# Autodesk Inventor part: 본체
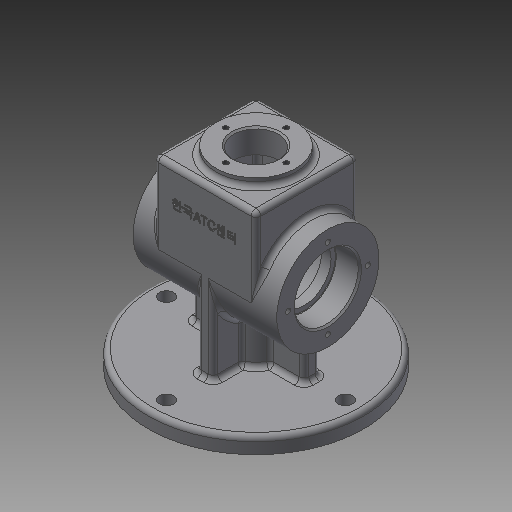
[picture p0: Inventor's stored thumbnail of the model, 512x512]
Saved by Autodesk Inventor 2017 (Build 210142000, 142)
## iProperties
Created: 2020-07
Part Number: 본체
Material: 일반
Document SubType Name: Modeling
Designer: mduedu
Density: 1 g/cm^3
Appearance: 기본값
Author: mduedu
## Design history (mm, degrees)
sketch "스케치1"
  geometry: C1 r 32 at (0, 0); 1 further point
  constraints: 1 centre point, 1 coincident
  dimensions: "d0" = 64 diameter of C1
extrude "돌출1" new body sketch "스케치1" stored distance "d1" = 90; taper "d2" = 0 deg
sketch "스케치3"
  geometry: L1 (0, -32)-(50, -32); L2 (50, -32)-(50, 32); L3 (50, 32)-(0, 32); L4 (0, 32)-(0, -32); C1 r 32 at (0, 0) reference; 2 further points
  constraints: 8 end point, 2 parallel, 1 coincident, 1 horizontal, 1 midpoint, 1 perpendicular, 1 tangent
  dimensions: "d5" = 50 distance of L2.end L3.end
extrude "돌출2" join sketch "스케치3" stored distance "d7" = 64; taper "d8" = 0 deg
sketch "스케치4"
  geometry: C1 r 25 at (32, 32); 1 further point
  constraints: 1 centre point, 1 coincident
  dimensions: "d9" = 50 diameter of C1
extrude "돌출3" join sketch "스케치4" distance "d10" = 5; taper "d11" = 0 deg
sketch "스케치5"
  geometry: L1 (0, -25)-(40, -25); L2 (40, -25)-(40, 25); L3 (40, 25)-(0, 25); L4 (0, 25)-(0, -25); L5 (55, -25)-(55, 25) reference; A1 r 25 centre (0, 0) between (0, 25) and (0, -25); A2 r 25 centre (0, 0) between (0, -25) and (0, 25); 2 further points
  constraints: 8 end point, 4 point on circle, 2 centre point, 2 coincident, 2 parallel, 1 horizontal, 1 midpoint, 1 perpendicular, 1 tangent
  dimensions: "d12" = 50 diameter of A1; "d13" = 15 distance between parallel lines of L2 L5
extrude "돌출4" cut sketch "스케치5" stored distance "d14" = 48; taper "d15" = 0 deg
sketch "스케치6"
  geometry: C1 r 20 at (0, 0); 1 further point
  constraints: 1 centre point, 1 coincident
  dimensions: "d16" = 40 diameter of C1
extrude "돌출5" cut sketch "스케치6" distance "d17" = 15; taper "d18" = 0 deg
sketch "스케치7"
  geometry: C1 r 17 at (0, 0); 1 further point
  constraints: 1 centre point, 1 coincident
  dimensions: "d19" = 34 diameter of C1
extrude "돌출6" cut sketch "스케치7" stored distance "d20" = 15; taper "d21" = 0 deg
fillet "모깎기1" dims "d22" = 3
fillet "모깎기2" dims "d23" = 3
fillet "모깎기3" dims "d24" = 3
fillet "모깎기4" dims "d25" = 3
fillet "모깎기5" dims "d26" = 3
sketch "스케치8"
  geometry: C1 r 14 at (0, 0); 1 further point
  constraints: 1 centre point, 1 coincident
  dimensions: "d27" = 28 diameter of C1
extrude "돌출7" cut sketch "스케치8" stored distance "d28" = 15; taper "d29" = 0 deg
node "작업 평면1"
sketch "스케치9"
  geometry: C1 r 67.5 at (0, 0); 1 further point
  constraints: 1 centre point, 1 coincident
  dimensions: "d31" = 135 diameter of C1
extrude "돌출8" join sketch "스케치9" distance "d33" = 10; taper "d34" = 0 deg
sketch "스케치10"
  geometry: C1 r 15 at (0, 0); 1 further point
  constraints: 1 centre point, 1 coincident
  dimensions: "d35" = 30 diameter of C1
extrude "돌출9" join sketch "스케치10" stored distance "d39" = 10; taper "d40" = 0 deg
sketch "스케치11"
  geometry: L1 (-35, -5)-(35, -5); L2 (35, -5)-(35, 5); L3 (35, 5)-(-35, 5); L4 (-35, 5)-(-35, -5); L5 (-35, -5)-(35, 5); L6 (35, -5)-(-35, 5); 1 further point
  constraints: 12 end point, 2 midpoint, 2 parallel, 1 horizontal, 1 perpendicular
  dimensions: "d41" = 70 distance of L3.end L2.end; "d42" = 10 distance of L2.end L1.end
extrude "돌출10" join sketch "스케치11" stored distance "d43" = 10; taper "d44" = 0 deg
sketch "스케치12"
  geometry: L1 (-5, -32)-(5, -32); L2 (5, -32)-(5, 32); L3 (5, 32)-(-5, 32); L4 (-5, 32)-(-5, -32); L5 (-5, -32)-(5, 32); L6 (5, -32)-(-5, 32); 1 further point
  constraints: 12 end point, 2 midpoint, 2 parallel, 1 horizontal, 1 perpendicular
  dimensions: "d45" = 10 distance of L3.end L2.end; "d46" = 64 distance of L2.end L1.end
extrude "돌출11" join sketch "스케치12" stored distance "d47" = 10; taper "d48" = 0 deg
fillet "모깎기6" dims "d50" = 3
fillet "모깎기7" dims "d51" = 3
sketch "스케치13" dims "d52" = 112
  geometry: 3 further points
  constraints: 2 horizontal alignment, 1 coincident, 2 other
hole "구멍1" sketch "스케치13" at (-56, 0) diameter "d54" = 9; stored, may be unused: countersink angle "d58" = 90 deg, drill point angle "d60" = 118 deg; dims "d55" = 6, "d56" = 4, "d57" = 2, "d59" = 8
fillet "모깎기8" dims "d64" = 3
sketch "스케치14" dims "d67" = 50
  geometry: 3 further points
  constraints: 2 vertical alignment, 1 coincident, 2 other
hole "구멍2" sketch "스케치14" at (0, 25) diameter "d68" = 3.242; stored, may be unused: countersink angle "d72" = 90 deg, drill point angle "d74" = 118 deg; dims "d69" = 7, "d70" = 4, "d71" = 2, "d73" = 9
sketch "스케치15" dims "d78" = 38
  geometry: 3 further points
  constraints: 2 vertical alignment, 1 coincident, 2 other
hole "구멍3" sketch "스케치15" at (0, 19) diameter "d79" = 3.242; stored, may be unused: countersink angle "d83" = 90 deg, drill point angle "d85" = 118 deg; dims "d80" = 8, "d81" = 4, "d82" = 2, "d84" = 10
fillet "모깎기9" dims "d89" = 0.3
chamfer "모따기1" distance "d90" = 1; stored, may be unused: second distance "d91" = 2, angle "d92" = 45 deg
chamfer "모따기2" distance "d93" = 1; stored, may be unused: second distance "d94" = 2, angle "d95" = 45 deg
sketch "스케치16"
  geometry: L1 (-3, 0)-(-3, -27.404) reference; L2 (54, 8)-(4, 8) reference; 2 further points
  constraints: 1 other
  dimensions: "d96" = 32 distance from line of point (29, -17) L1; "d97" = 25 distance from line of point (29, -17) L2
feature "엠보싱1" sketch "스케치16" dims "d0" = 64, "d98" = 0.5, "d99" = 0
node "솔리드1"
mirror "대칭1"
pattern_circular "원형 패턴1" dims angle "d62" = 360 deg
pattern_circular "원형 패턴2" dims angle "d76" = 360 deg
mirror "대칭2"
pattern_circular "원형 패턴3" dims angle "d87" = 360 deg
other parameters: "d30" = -65
